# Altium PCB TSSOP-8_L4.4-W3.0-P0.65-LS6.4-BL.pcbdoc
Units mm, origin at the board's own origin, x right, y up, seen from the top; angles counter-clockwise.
Board outline 15.7 x 20.1 mm, 2 copper layers (Top Layer, Bottom Layer), stack 0 mm thick; 1 components, 0 nets, 8 pads, 0 vias.
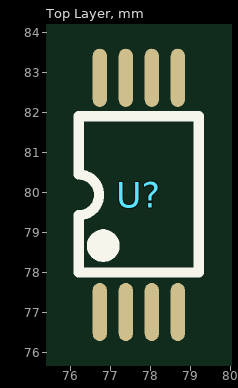
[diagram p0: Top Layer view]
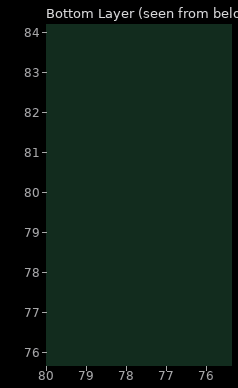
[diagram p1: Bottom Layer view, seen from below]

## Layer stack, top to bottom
Top Layer: signal copper (thickness not stored)
Bottom Layer: signal copper (thickness not stored)

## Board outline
85.551,69.85 69.85,69.85 69.85,89.954 85.551,89.954

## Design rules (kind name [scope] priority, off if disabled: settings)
PasteMaskExpansion "Paste Mask Expansion" [All] p1: expansion=0
SolderMaskExpansion "Solder Mask Expansion" [IsVia] p1: expansion=-25.4 istentingtop=TRUE
SolderMaskExpansion "Solder Mask Expansion" [All] p2: expansion=0.051 istentingtop=FALSE

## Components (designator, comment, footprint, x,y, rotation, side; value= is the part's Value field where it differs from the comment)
U? "" TSSOP-8_L4.4-W3.0-P0.65-LS6.4-BL 77.701,79.95 r0 top

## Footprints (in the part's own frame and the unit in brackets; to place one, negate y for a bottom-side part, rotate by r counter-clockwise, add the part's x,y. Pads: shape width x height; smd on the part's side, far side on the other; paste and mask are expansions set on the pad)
TSSOP-8_L4.4-W3.0-P0.65-LS6.4-BL [mm]
  oval 0.353x1.454 smd: 1(-0.975,-2.927) 2(-0.325,-2.927) 3(0.325,-2.927) 4(0.975,-2.927) 5(0.975,2.927) 6(0.325,2.927) 7(-0.325,2.927) 8(-0.975,2.927)
  silkscreen extent -1.5,-1.94 1.5,1.97

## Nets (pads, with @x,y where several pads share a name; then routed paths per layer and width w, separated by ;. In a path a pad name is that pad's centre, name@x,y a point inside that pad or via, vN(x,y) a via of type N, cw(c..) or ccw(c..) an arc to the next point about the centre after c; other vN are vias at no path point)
pads on no net: U?.1 U?.2 U?.3 U?.4 U?.5 U?.6 U?.7 U?.8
